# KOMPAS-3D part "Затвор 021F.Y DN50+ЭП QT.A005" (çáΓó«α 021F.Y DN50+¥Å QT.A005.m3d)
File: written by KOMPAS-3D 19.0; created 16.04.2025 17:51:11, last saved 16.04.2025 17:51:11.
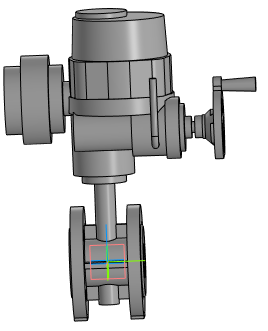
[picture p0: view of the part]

Document properties: Полное имя файла: Затвор 021F.Y DN50+ЭП QT.A005.a3d

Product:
- Part/product: Затвор 021F.Y DN50+ЭП QT.A005
    Масса: 43.9613

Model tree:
1. Операция без истории:1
